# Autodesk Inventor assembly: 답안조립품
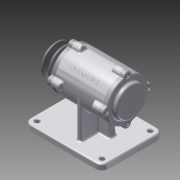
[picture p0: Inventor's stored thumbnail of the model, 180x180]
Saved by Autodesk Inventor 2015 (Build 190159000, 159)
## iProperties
Created: 2015-12
Part Number: 답안조립품
Document SubType Name: Assembly
Designer: 601-23
Author: 601-23
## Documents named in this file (11)
- C:\Users\601-23\Desktop\451208V1029\답안조립품.iam
- C:\Users\601-23\Desktop\451208V1029\본체.ipt
- C:\Users\601-23\Desktop\451208V1029\커버2.ipt
- C:\Users\601-23\Desktop\451208V1029\베어링 6204.ipt
- C:\Users\601-23\Desktop\451208V1029\축.ipt
- C:\Users\601-23\Desktop\451208V1029\커버.ipt
- C:\Users\601-23\Desktop\451208V1029\오일실.ipt
- C:\Users\601-23\Desktop\451208V1029\V-벨트풀리.ipt
- C:\Users\601-23\Desktop\451208V1029\키(4 x 4 x 12).ipt
- C:\Users\601-23\Desktop\451208V1029\너트 M12x1.25.ipt
- C:\Users\601-23\Desktop\451208V1029\볼트 M4 x 12.ipt
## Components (6 placed, 5 different names)
1. KS B 2023 6204 - 20 x 47 x 14:1
2. KS B 2023 6204 - 20 x 47 x 14:2
3. KS B 2804 D D - 20 32 8:1
4. V-벨트풀리:1 — 각도:2
5. KS B 1311 (I) 4 x 4 x 12:1 — 각도:2
6. KS B 1012 클래스 1 일반 - 미터 M12x1.25:1
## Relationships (1: Angle 1)
- 각도:2 [Angle]: V-벨트풀리:1 ↔ KS B 1311 (I) 4 x 4 x 12:1
